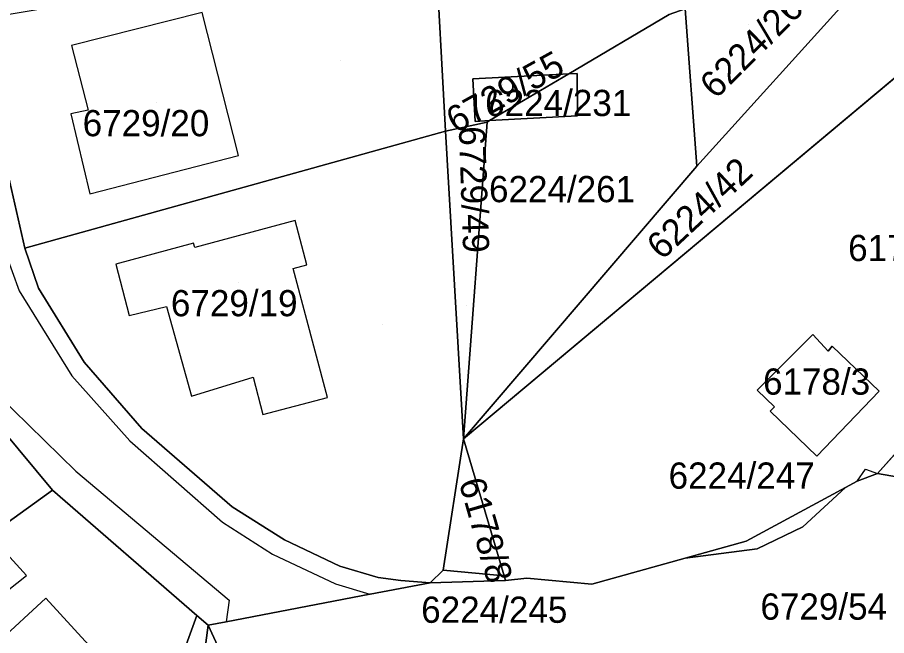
# Model space of a CAD drawing. Extents: x -266199 to -261993, y -1239047 to -1235108.
# Drawn here: x -264005.4 to -263939.1, y -1236308.7 to -1236261.5 of the extents above; entities that cross this region are included whole.
import ezdxf

# ---------------------------------------------------------------- set-up
doc = ezdxf.new("R2010")
doc.units = 0
for name, color, linetype in [('body_kn', 7, 'Continuous'), ('kladpar_druhypozemkov', 7, 'Continuous'), ('kladpar_hranice', 7, 'Continuous'), ('kladpar_parcelnecisla', 7, 'Continuous'), ('kladpar_plochy', 7, 'Continuous'), ('kladpar_sipky', 7, 'Continuous'), ('zappar_hrandruhpozemk', 7, 'Continuous')]:
    doc.layers.add(name, color=color, linetype=linetype)

msp = doc.modelspace()

# ---------------------------------------------------------------- linework, layer by layer
at = {"layer": 'body_kn'}
for p, q in [((-264001.26, -1236263.7), (-264001.26, -1236263.7)), ((-263963.32, -1236265.85), (-263963.32, -1236265.85)), ((-263963.32, -1236265.85), (-263963.32, -1236265.85)), ((-263962.67, -1236265.82), (-263962.67, -1236265.82)), ((-263970.63, -1236266.23), (-263970.63, -1236266.23)), ((-264000, -1236268.63), (-264000, -1236268.63)), ((-264001.33, -1236268.9), (-264001.33, -1236268.9)), ((-263970.47, -1236269.48), (-263970.47, -1236269.48)), ((-263969.36, -1236269.42), (-263969.36, -1236269.42)), ((-263969.36, -1236269.42), (-263969.36, -1236269.42)), ((-263962.64, -1236269.04), (-263962.64, -1236269.04)), ((-263969.55, -1236269.53), (-263969.55, -1236269.53)), ((-263969.55, -1236269.53), (-263969.55, -1236269.53)), ((-263972.72, -1236270.21), (-263972.72, -1236270.21)), ((-263972.72, -1236270.21), (-263972.72, -1236270.21)), ((-263988.51, -1236272.09), (-263988.51, -1236272.09)), ((-263988.51, -1236272.09), (-263988.51, -1236272.09)), ((-263953.55, -1236272.88), (-263953.55, -1236272.88)), ((-263953.55, -1236272.88), (-263953.55, -1236272.88)), ((-263999.86, -1236274.99), (-263999.86, -1236274.99)), ((-263984.21, -1236277.04), (-263984.21, -1236277.04)), ((-263991.95, -1236278.76), (-263991.95, -1236278.76)), ((-264004.83, -1236279.14), (-264004.83, -1236279.14)), ((-264004.83, -1236279.14), (-264004.83, -1236279.14)), ((-263991.86, -1236279.09), (-263991.86, -1236279.09)), ((-263997.89, -1236280.36), (-263997.89, -1236280.36)), ((-263984.36, -1236280.7), (-263984.36, -1236280.7)), ((-263983.31, -1236280.42), (-263983.31, -1236280.42)), ((-264005.26, -1236282.41), (-264005.26, -1236282.41)), ((-264003.8, -1236282.2), (-264003.8, -1236282.2)), ((-263994.03, -1236283.59), (-263994.03, -1236283.59)), ((-263996.87, -1236284.28), (-263996.87, -1236284.28)), ((-263944.68, -1236285.73), (-263944.68, -1236285.73)), ((-263943.21, -1236286.63), (-263943.21, -1236286.63)), ((-263943.52, -1236286.99), (-263943.52, -1236286.99)), ((-264000.31, -1236287.84), (-264000.31, -1236287.84)), ((-264001.25, -1236288.87), (-264001.25, -1236288.87)), ((-263987.4, -1236288.99), (-263987.4, -1236288.99)), ((-263948.94, -1236289.97), (-263948.94, -1236289.97)), ((-263939.61, -1236290.06), (-263939.61, -1236290.06)), ((-263939.61, -1236290.06), (-263939.61, -1236290.06)), ((-263992.11, -1236290.44), (-263992.11, -1236290.44)), ((-263981.72, -1236290.53), (-263981.72, -1236290.53)), ((-263981.72, -1236290.53), (-263981.72, -1236290.53)), ((-263947.62, -1236291.24), (-263947.62, -1236291.24)), ((-263986.66, -1236291.82), (-263986.66, -1236291.82)), ((-263947.93, -1236291.57), (-263947.93, -1236291.57)), ((-263995.9, -1236292.89), (-263995.9, -1236292.89)), ((-263996.81, -1236293.85), (-263996.81, -1236293.85)), ((-263971.35, -1236293.7), (-263971.35, -1236293.7)), ((-263971.35, -1236293.7), (-263971.35, -1236293.7)), ((-263944.37, -1236295), (-263944.37, -1236295)), ((-263940.66, -1236295.99), (-263940.66, -1236295.99)), ((-264000.94, -1236296.16), (-264000.94, -1236296.16)), ((-263939.74, -1236296.32), (-263939.74, -1236296.32)), ((-263939.74, -1236296.32), (-263939.74, -1236296.32)), ((-263941.3, -1236296.92), (-263941.3, -1236296.92)), ((-263941.3, -1236296.92), (-263941.3, -1236296.92)), ((-264002.73, -1236297.6), (-264002.73, -1236297.6)), ((-264002.73, -1236297.6), (-264002.73, -1236297.6)), ((-263942.19, -1236297.4), (-263942.19, -1236297.4)), ((-263942.19, -1236297.4), (-263942.19, -1236297.4)), ((-263989.01, -1236298.87), (-263989.01, -1236298.87)), ((-263989.74, -1236300.05), (-263989.74, -1236300.05)), ((-263945.44, -1236300.39), (-263945.44, -1236300.39)), ((-263985.02, -1236301.39), (-263985.02, -1236301.39)), ((-263949.77, -1236301.49), (-263949.77, -1236301.49)), ((-263985.92, -1236302.49), (-263985.92, -1236302.49)), ((-263948.94, -1236302.07), (-263948.94, -1236302.07)), ((-263954.42, -1236302.79), (-263954.42, -1236302.79)), ((-263954.42, -1236302.79), (-263954.42, -1236302.79)), ((-263980.8, -1236303.4), (-263980.8, -1236303.4)), ((-263972.89, -1236303.7), (-263972.89, -1236303.7)), ((-263972.89, -1236303.7), (-263972.89, -1236303.7)), ((-264004.7, -1236304.11), (-264004.7, -1236304.11)), ((-263977.86, -1236304.26), (-263977.86, -1236304.26)), ((-263976.12, -1236304.5), (-263976.12, -1236304.5)), ((-263973.9, -1236304.67), (-263973.9, -1236304.67)), ((-263973.9, -1236304.67), (-263973.9, -1236304.67)), ((-263968.25, -1236304.14), (-263968.25, -1236304.14)), ((-263968.25, -1236304.14), (-263968.25, -1236304.14)), ((-263968.14, -1236304.5), (-263968.14, -1236304.5)), ((-263966.52, -1236304.31), (-263966.52, -1236304.31)), ((-263981.13, -1236304.75), (-263981.13, -1236304.75)), ((-263961.55, -1236304.78), (-263961.55, -1236304.78)), ((-264003.23, -1236305.85), (-264003.23, -1236305.85)), ((-263989.23, -1236305.99), (-263989.23, -1236305.99)), ((-263978.5, -1236305.54), (-263978.5, -1236305.54)), ((-263978.5, -1236305.54), (-263978.5, -1236305.54)), ((-263978.48, -1236305.54), (-263978.48, -1236305.54)), ((-263991.7, -1236307.15), (-263991.7, -1236307.15)), ((-263991.7, -1236307.15), (-263991.7, -1236307.15)), ((-263990.84, -1236307.9), (-263990.84, -1236307.9)), ((-263990.84, -1236307.9), (-263990.84, -1236307.9)), ((-263989.46, -1236307.64), (-263989.46, -1236307.64))]:
    msp.add_line(p, q, dxfattribs=at)
at = {"layer": 'kladpar_druhypozemkov'}
for p, q in [((-263949.57, -1236262.06), (-263949.57, -1236262.06)), ((-263980.72, -1236264.82), (-263980.72, -1236264.82)), ((-263968.38, -1236266.69), (-263968.38, -1236266.69)), ((-263994.75, -1236268.01), (-263994.75, -1236268.01)), ((-263964.05, -1236267.79), (-263964.05, -1236267.79)), ((-263963.65, -1236273.83), (-263963.65, -1236273.83)), ((-263953.16, -1236274.73), (-263953.16, -1236274.73)), ((-263988.54, -1236281.74), (-263988.54, -1236281.74)), ((-263971.12, -1236283.52), (-263971.12, -1236283.52)), ((-263977.5, -1236284.94), (-263977.5, -1236284.94)), ((-263944.11, -1236288.1), (-263944.11, -1236288.1)), ((-263971.11, -1236297.87), (-263971.11, -1236297.87)), ((-263946.82, -1236300.82), (-263946.82, -1236300.82)), ((-263971.21, -1236304.41), (-263971.21, -1236304.41))]:
    msp.add_line(p, q, dxfattribs=at)
at = {"layer": 'kladpar_hranice'}
for p, q in [((-263963.32, -1236265.85), (-263969.36, -1236269.42)), ((-263969.36, -1236269.42), (-263963.32, -1236265.85)), ((-263969.55, -1236269.53), (-263969.36, -1236269.42)), ((-263971.35, -1236293.7), (-263969.55, -1236269.53)), ((-263971.35, -1236293.7), (-263972.72, -1236270.21)), ((-263971.35, -1236293.7), (-263953.55, -1236272.88)), ((-263971.35, -1236293.7), (-263972.89, -1236303.7)), ((-263971.35, -1236293.7), (-263968.25, -1236304.14)), ((-264022.4, -1236311.79), (-264002.73, -1236297.6)), ((-264002.73, -1236297.6), (-263991.7, -1236307.15)), ((-263972.89, -1236303.7), (-263973.9, -1236304.67)), ((-263973.9, -1236304.67), (-263972.89, -1236303.7)), ((-263972.89, -1236303.7), (-263968.25, -1236304.14)), ((-264003.85, -1236340.48), (-263991.7, -1236307.15)), ((-263991.7, -1236307.15), (-264003.85, -1236340.48)), ((-263991.7, -1236307.15), (-263990.84, -1236307.9)), ((-263992.13, -1236317.75), (-263990.84, -1236307.9))]:
    msp.add_line(p, q, dxfattribs=at)
for points in [[(-263990.84, -1236307.9), (-263991.7, -1236307.15), (-264002.73, -1236297.6), (-264009.24, -1236289.8), (-264013.5, -1236282.12), (-264016.21, -1236263.53), (-264016.19, -1236262.99), (-264015.46, -1236245.3), (-264014.2, -1236226.69), (-264013.5, -1236207.26), (-264012.31, -1236189.03), (-264011.29, -1236170.91)], [(-263939.74, -1236296.32), (-263935.82, -1236297.03), (-263934.58, -1236297.27), (-263923.4, -1236283.81), (-263912.8, -1236268.14), (-263907.81, -1236254.71), (-263903.15, -1236237.4), (-263904.63, -1236222.89), (-263904.13, -1236219.7), (-263903.08, -1236212.9), (-263903.59, -1236195.15), (-263904.36, -1236178.51)], [(-263972.72, -1236270.21), (-263973.52, -1236255.75), (-263975.06, -1236228.6)], [(-263971.35, -1236293.7), (-263937.45, -1236265.34), (-263935.46, -1236254.01), (-263933.47, -1236228.53)], [(-263903.96, -1236237.26), (-263910.67, -1236252.45), (-263911.28, -1236253.99), (-263916.97, -1236266.71), (-263925.84, -1236279.74), (-263935.1, -1236291.13), (-263939.74, -1236296.32)], [(-263934.58, -1236297.27), (-263935.82, -1236297.03), (-263939.74, -1236296.32), (-263935.1, -1236291.13), (-263925.84, -1236279.74), (-263916.97, -1236266.71), (-263911.28, -1236253.99), (-263910.67, -1236252.45), (-263903.96, -1236237.26), (-263903.74, -1236237.3), (-263903.15, -1236237.4), (-263907.81, -1236254.71), (-263912.8, -1236268.14), (-263923.4, -1236283.81), (-263934.58, -1236297.27)], [(-263935.46, -1236254.01), (-263937.45, -1236265.34), (-263971.35, -1236293.7)], [(-264004.83, -1236279.14), (-264006.37, -1236272.43), (-264007.4, -1236261.54), (-263989.57, -1236258.49), (-263973.52, -1236255.75), (-263972.72, -1236270.21), (-264004.83, -1236279.14)], [(-263940.64, -1236255.89), (-263941.66, -1236259.76), (-263953.55, -1236272.88), (-263954.42, -1236260.88)], [(-263953.55, -1236272.88), (-263941.66, -1236259.76), (-263940.64, -1236255.89)], [(-263954.42, -1236260.88), (-263953.55, -1236272.88), (-263971.35, -1236293.7)], [(-263954.42, -1236260.88), (-263955.66, -1236261.33), (-263963.32, -1236265.85)], [(-263963.32, -1236265.85), (-263955.66, -1236261.33), (-263954.42, -1236260.88)], [(-263963.32, -1236265.85), (-263970.63, -1236266.23), (-263970.47, -1236269.48), (-263969.36, -1236269.42)], [(-263969.36, -1236269.42), (-263970.47, -1236269.48), (-263970.63, -1236266.23), (-263963.32, -1236265.85)], [(-263969.36, -1236269.42), (-263962.64, -1236269.04), (-263962.67, -1236265.82), (-263963.32, -1236265.85)], [(-263963.32, -1236265.85), (-263962.67, -1236265.82), (-263962.64, -1236269.04), (-263969.36, -1236269.42)], [(-263969.36, -1236269.42), (-263969.55, -1236269.53), (-263972.72, -1236270.21)], [(-263972.72, -1236270.21), (-263969.55, -1236269.53), (-263971.35, -1236293.7)], [(-263973.9, -1236304.67), (-263976.12, -1236304.5), (-263977.86, -1236304.26), (-263980.8, -1236303.4), (-263985.02, -1236301.39), (-263989.01, -1236298.87), (-263995.9, -1236292.89), (-264000.31, -1236287.84), (-264003.8, -1236282.2), (-264004.83, -1236279.14), (-263972.72, -1236270.21), (-263971.35, -1236293.7)], [(-264006.37, -1236272.43), (-264004.83, -1236279.14), (-264003.8, -1236282.2), (-264000.31, -1236287.84), (-263995.9, -1236292.89), (-263989.01, -1236298.87), (-263985.02, -1236301.39), (-263980.8, -1236303.4), (-263977.86, -1236304.26), (-263976.12, -1236304.5), (-263973.9, -1236304.67), (-263978.48, -1236305.54), (-263978.5, -1236305.54), (-263989.46, -1236307.64), (-263990.84, -1236307.9)], [(-264047.49, -1236295.22), (-264016.41, -1236282.14), (-264013.5, -1236282.12), (-264009.24, -1236289.8), (-264002.73, -1236297.6), (-264022.4, -1236311.79), (-264032.48, -1236318.83), (-264039.72, -1236323.88), (-264044.08, -1236326.93), (-264044.86, -1236327.48)], [(-263944.37, -1236295), (-263939.61, -1236290.06), (-263943.21, -1236286.63), (-263943.52, -1236286.99), (-263944.68, -1236285.73), (-263948.94, -1236289.97), (-263947.62, -1236291.24), (-263947.93, -1236291.57), (-263944.37, -1236295)], [(-263939.61, -1236290.06), (-263944.37, -1236295), (-263947.93, -1236291.57), (-263947.62, -1236291.24), (-263948.94, -1236289.97), (-263944.68, -1236285.73), (-263943.52, -1236286.99), (-263943.21, -1236286.63), (-263939.61, -1236290.06)], [(-263968.25, -1236304.14), (-263972.89, -1236303.7), (-263971.35, -1236293.7)], [(-263966.52, -1236304.31), (-263968.14, -1236304.5), (-263968.25, -1236304.14), (-263971.35, -1236293.7)], [(-263939.74, -1236296.32), (-263941.3, -1236296.92), (-263942.19, -1236297.4), (-263949.77, -1236301.49), (-263954.42, -1236302.79), (-263961.55, -1236304.78), (-263966.52, -1236304.31)], [(-263942.19, -1236297.4), (-263941.3, -1236296.92), (-263939.74, -1236296.32)], [(-263942.19, -1236297.4), (-263945.44, -1236300.39), (-263948.94, -1236302.07), (-263954.42, -1236302.79)], [(-263954.42, -1236302.79), (-263949.77, -1236301.49), (-263942.19, -1236297.4)], [(-263954.42, -1236302.79), (-263948.94, -1236302.07), (-263945.44, -1236300.39), (-263942.19, -1236297.4)], [(-263966.52, -1236304.31), (-263961.55, -1236304.78), (-263954.42, -1236302.79)], [(-263990.84, -1236307.9), (-263989.46, -1236307.64), (-263978.5, -1236305.54), (-263978.48, -1236305.54), (-263973.9, -1236304.67), (-263968.14, -1236304.5), (-263966.52, -1236304.31)], [(-263968.25, -1236304.14), (-263968.14, -1236304.5), (-263973.9, -1236304.67)], [(-263990.84, -1236307.9), (-263992.13, -1236317.75), (-263993.88, -1236331.16)], [(-263990.84, -1236307.9), (-263989.81, -1236310.12), (-263989.6, -1236310.58), (-263990.07, -1236311.9), (-263992.13, -1236317.75)], [(-263992.13, -1236317.75), (-263990.07, -1236311.9), (-263989.6, -1236310.58), (-263989.81, -1236310.12), (-263990.84, -1236307.9)]]:
    msp.add_lwpolyline(points, dxfattribs=at)
at = {"layer": 'kladpar_plochy'}
for p, q in [((-263971.35, -1236293.7), (-263937.45, -1236265.34)), ((-263944.68, -1236285.73), (-263948.94, -1236289.97)), ((-263943.52, -1236286.99), (-263944.68, -1236285.73)), ((-263943.21, -1236286.63), (-263943.52, -1236286.99)), ((-263939.61, -1236290.06), (-263943.21, -1236286.63)), ((-263948.94, -1236289.97), (-263947.62, -1236291.24)), ((-263944.37, -1236295), (-263939.61, -1236290.06)), ((-263947.62, -1236291.24), (-263947.93, -1236291.57)), ((-263935.1, -1236291.13), (-263939.74, -1236296.32)), ((-263947.93, -1236291.57), (-263944.37, -1236295)), ((-263968.25, -1236304.14), (-263971.35, -1236293.7)), ((-263939.74, -1236296.32), (-263941.3, -1236296.92)), ((-263941.3, -1236296.92), (-263939.74, -1236296.32)), ((-263939.74, -1236296.32), (-263935.82, -1236297.03)), ((-263941.3, -1236296.92), (-263942.19, -1236297.4)), ((-263942.19, -1236297.4), (-263941.3, -1236296.92)), ((-263942.19, -1236297.4), (-263949.77, -1236301.49)), ((-263945.44, -1236300.39), (-263942.19, -1236297.4)), ((-263948.94, -1236302.07), (-263945.44, -1236300.39)), ((-263949.77, -1236301.49), (-263954.42, -1236302.79)), ((-263954.42, -1236302.79), (-263948.94, -1236302.07)), ((-263954.42, -1236302.79), (-263961.55, -1236304.78)), ((-263961.55, -1236304.78), (-263954.42, -1236302.79)), ((-263978.48, -1236305.54), (-263973.9, -1236304.67)), ((-263973.9, -1236304.67), (-263968.14, -1236304.5)), ((-263968.14, -1236304.5), (-263968.25, -1236304.14)), ((-263966.52, -1236304.31), (-263968.14, -1236304.5)), ((-263968.14, -1236304.5), (-263966.52, -1236304.31)), ((-263961.55, -1236304.78), (-263966.52, -1236304.31)), ((-263966.52, -1236304.31), (-263961.55, -1236304.78)), ((-263989.46, -1236307.64), (-263978.5, -1236305.54)), ((-263978.5, -1236305.54), (-263978.48, -1236305.54)), ((-263990.84, -1236307.9), (-263989.46, -1236307.64)), ((-263989.81, -1236310.12), (-263990.84, -1236307.9))]:
    msp.add_line(p, q, dxfattribs=at)
for points in [[(-263975.06, -1236228.6), (-263956.86, -1236227.23), (-263954.42, -1236260.88), (-263955.66, -1236261.33), (-263963.32, -1236265.85), (-263970.63, -1236266.23), (-263970.47, -1236269.48), (-263969.36, -1236269.42), (-263969.55, -1236269.53), (-263972.72, -1236270.21), (-263973.52, -1236255.75)], [(-263934.58, -1236297.27), (-263935.82, -1236297.03), (-263939.74, -1236296.32), (-263935.1, -1236291.13), (-263925.84, -1236279.74), (-263916.97, -1236266.71), (-263911.28, -1236253.99), (-263910.67, -1236252.45), (-263903.96, -1236237.26), (-263903.74, -1236237.3), (-263903.15, -1236237.4), (-263907.81, -1236254.71), (-263912.8, -1236268.14), (-263923.4, -1236283.81)], [(-263953.55, -1236272.88), (-263941.66, -1236259.76), (-263940.64, -1236255.89), (-263935.46, -1236254.01), (-263937.45, -1236265.34), (-263971.35, -1236293.7)], [(-264004.83, -1236279.14), (-264006.37, -1236272.43), (-264007.4, -1236261.54), (-263989.57, -1236258.49), (-263973.52, -1236255.75), (-263972.72, -1236270.21)], [(-263954.42, -1236260.88), (-263940.64, -1236255.89), (-263941.66, -1236259.76), (-263953.55, -1236272.88)], [(-263969.55, -1236269.53), (-263969.36, -1236269.42), (-263962.64, -1236269.04), (-263962.67, -1236265.82), (-263963.32, -1236265.85), (-263955.66, -1236261.33), (-263954.42, -1236260.88), (-263953.55, -1236272.88), (-263971.35, -1236293.7)], [(-263969.36, -1236269.42), (-263970.47, -1236269.48), (-263970.63, -1236266.23), (-263963.32, -1236265.85)], [(-263963.32, -1236265.85), (-263962.67, -1236265.82), (-263962.64, -1236269.04), (-263969.36, -1236269.42)], [(-263971.35, -1236293.7), (-263972.72, -1236270.21), (-263969.55, -1236269.53)], [(-263973.9, -1236304.67), (-263976.12, -1236304.5), (-263977.86, -1236304.26), (-263980.8, -1236303.4), (-263985.02, -1236301.39), (-263989.01, -1236298.87), (-263995.9, -1236292.89), (-264000.31, -1236287.84), (-264003.8, -1236282.2), (-264004.83, -1236279.14), (-263972.72, -1236270.21), (-263971.35, -1236293.7), (-263972.89, -1236303.7)], [(-264047.49, -1236295.22), (-264016.41, -1236282.14), (-264013.5, -1236282.12), (-264009.24, -1236289.8), (-264002.73, -1236297.6), (-264022.4, -1236311.79), (-264032.48, -1236318.83), (-264039.72, -1236323.88), (-264044.08, -1236326.93), (-264044.86, -1236327.48)], [(-263939.61, -1236290.06), (-263944.37, -1236295), (-263947.93, -1236291.57), (-263947.62, -1236291.24), (-263948.94, -1236289.97), (-263944.68, -1236285.73), (-263943.52, -1236286.99), (-263943.21, -1236286.63)], [(-263971.35, -1236293.7), (-263968.25, -1236304.14), (-263972.89, -1236303.7)], [(-264002.73, -1236297.6), (-263991.7, -1236307.15), (-264003.85, -1236340.48), (-264005.64, -1236338.02), (-264011.01, -1236328.85), (-264012.4, -1236326.76), (-264022.4, -1236311.79)], [(-263942.19, -1236297.4), (-263945.44, -1236300.39), (-263948.94, -1236302.07), (-263954.42, -1236302.79), (-263949.77, -1236301.49)], [(-263973.9, -1236304.67), (-263972.89, -1236303.7), (-263968.25, -1236304.14), (-263968.14, -1236304.5)], [(-263990.84, -1236307.9), (-263992.13, -1236317.75), (-263993.88, -1236331.16), (-263996.25, -1236337.77), (-263996.72, -1236339.07), (-263997.67, -1236341.1), (-263999.36, -1236344.7), (-263995.86, -1236346.3), (-263996.19, -1236348.8), (-263997.03, -1236350.86), (-264000.89, -1236346.88), (-264000.92, -1236346.82), (-264002.8, -1236343.31), (-264005.64, -1236338.02), (-264003.85, -1236340.48), (-263991.7, -1236307.15)], [(-263992.13, -1236317.75), (-263990.84, -1236307.9), (-263989.81, -1236310.12), (-263989.6, -1236310.58), (-263990.07, -1236311.9)]]:
    msp.add_lwpolyline(points, close=True, dxfattribs=at)
msp.add_lwpolyline([(-264006.37, -1236272.43), (-264004.83, -1236279.14), (-264003.8, -1236282.2), (-264000.31, -1236287.84), (-263995.9, -1236292.89), (-263989.01, -1236298.87), (-263985.02, -1236301.39), (-263980.8, -1236303.4), (-263977.86, -1236304.26), (-263976.12, -1236304.5), (-263973.9, -1236304.67), (-263978.48, -1236305.54), (-263978.5, -1236305.54), (-263989.46, -1236307.64), (-263990.84, -1236307.9), (-263991.7, -1236307.15), (-264002.73, -1236297.6), (-264009.24, -1236289.8)], dxfattribs=at)
at = {"layer": 'kladpar_sipky'}
for p, q in [((-263948.53, -1236301.59), (-263948.53, -1236301.59)), ((-263969.58, -1236304.24), (-263969.58, -1236304.24))]:
    msp.add_line(p, q, dxfattribs=at)
at = {"layer": 'zappar_hrandruhpozemk'}
for p, q in [((-263988.51, -1236272.09), (-263991.3, -1236261.16)), ((-263981.72, -1236290.53), (-263984.36, -1236280.7)), ((-264005.26, -1236282.41), (-264001.25, -1236288.87)), ((-264008.25, -1236289.02), (-264000.94, -1236296.16)), ((-263941.3, -1236296.92), (-263940.66, -1236295.99)), ((-263940.66, -1236295.99), (-263939.74, -1236296.32)), ((-264009.56, -1236307.91), (-264004.7, -1236304.11)), ((-263978.5, -1236305.54), (-263978.48, -1236305.54))]:
    msp.add_line(p, q, dxfattribs=at)
for points in [[(-264008.54, -1236242.62), (-264008.9, -1236251.99), (-264008.95, -1236261.39), (-264007.92, -1236272.72), (-264006.34, -1236279.45), (-264005.26, -1236282.41)], [(-263991.3, -1236261.16), (-264001.26, -1236263.7), (-264000, -1236268.63), (-264001.33, -1236268.9), (-263999.86, -1236274.99), (-263988.51, -1236272.09)], [(-263984.36, -1236280.7), (-263983.31, -1236280.42), (-263984.21, -1236277.04), (-263991.86, -1236279.09), (-263991.95, -1236278.76), (-263997.89, -1236280.36), (-263996.87, -1236284.28), (-263994.03, -1236283.59), (-263992.11, -1236290.44), (-263987.4, -1236288.99), (-263986.66, -1236291.82), (-263981.72, -1236290.53)], [(-264001.25, -1236288.87), (-263996.81, -1236293.85), (-263989.74, -1236300.05), (-263985.92, -1236302.49), (-263981.13, -1236304.75), (-263978.5, -1236305.54)], [(-264000.94, -1236296.16), (-263989.23, -1236305.99), (-263989.46, -1236307.64)], [(-264004.7, -1236304.11), (-264007.02, -1236301.59), (-264011.61, -1236305.19), (-264009.56, -1236307.91)], [(-263995.58, -1236314.2), (-264003.23, -1236305.85), (-264010.63, -1236312.65), (-264011.82, -1236311.36), (-264013.39, -1236312.8), (-264008.23, -1236318.29), (-264006.88, -1236317.06), (-264003.13, -1236321.16)]]:
    msp.add_lwpolyline(points, dxfattribs=at)

# ---------------------------------------------------------------- texts
at = {"layer": 'kladpar_parcelnecisla'}
for s, rotation, p in [('6224/260', 45, (-263952.085, -1236267.839)), ('6729/55', 29, (-263971.937, -1236270.432)), ('6729/49', 272, (-263971.708, -1236269.878)), ('6224/42', 43, (-263956.198, -1236280.119)), ('6178/8', 286, (-263971.727, -1236296.98))]:
    msp.add_text(s, height=2, rotation=rotation, dxfattribs=at).set_placement(p)
for s, p in [('6224/231', (-263969.695, -1236269.07)), ('6729/20', (-264000.418, -1236270.61)), ('6224/261', (-263969.402, -1236275.64)), ('6178/2', (-263941.991, -1236280.13)), ('6729/19', (-263993.681, -1236284.34)), ('6178/3', (-263948.487, -1236290.32)), ('6224/247', (-263955.694, -1236297.49)), ('6224/245', (-263974.577, -1236307.72)), ('6729/54', (-263948.685, -1236307.48))]:
    msp.add_text(s, height=2, dxfattribs=at).set_placement(p)

doc.saveas('drawing.dxf')
